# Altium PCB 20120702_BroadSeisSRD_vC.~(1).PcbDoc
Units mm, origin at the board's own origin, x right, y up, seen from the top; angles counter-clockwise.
Board outline 68.5 x 51 mm, 4 copper layers (Top Layer, Mid-Layer 1, Mid-Layer 2, Bottom Layer); 59 components, 42 nets, 186 pads, 29 vias.
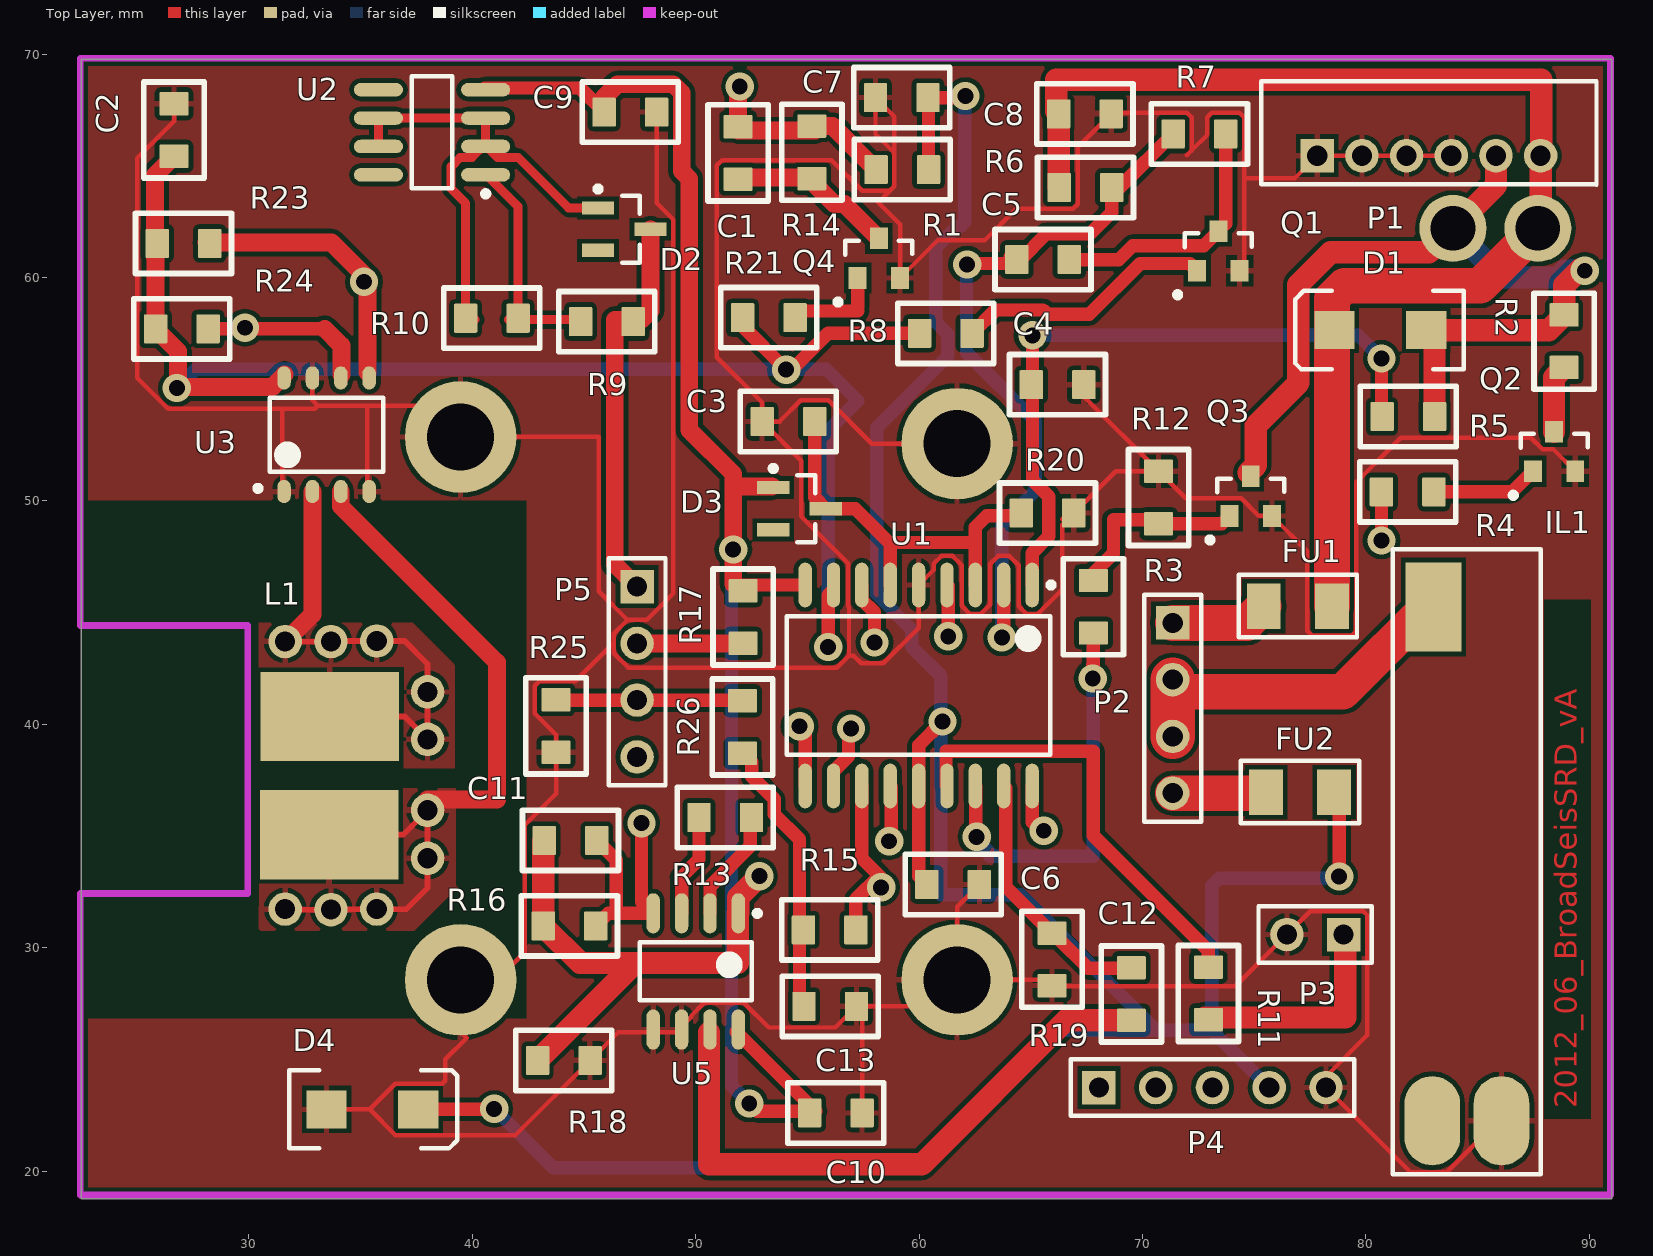
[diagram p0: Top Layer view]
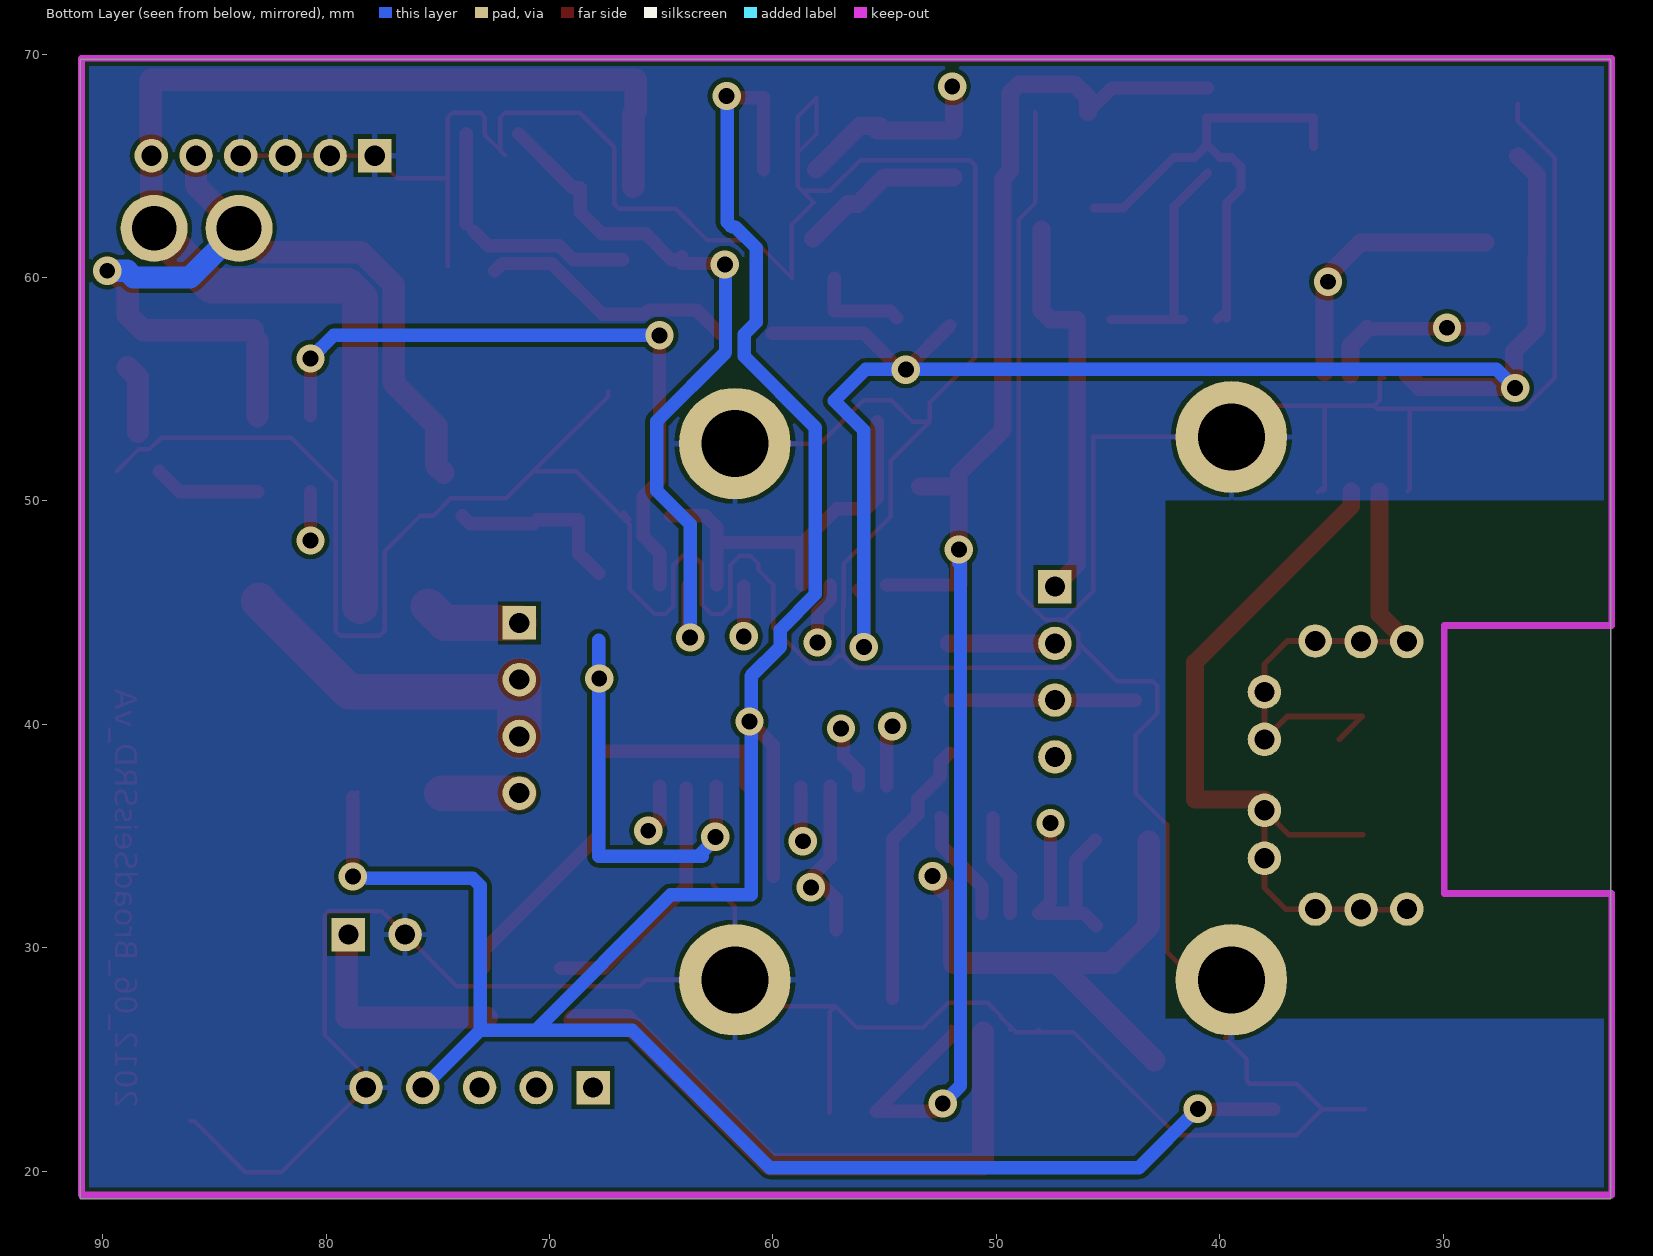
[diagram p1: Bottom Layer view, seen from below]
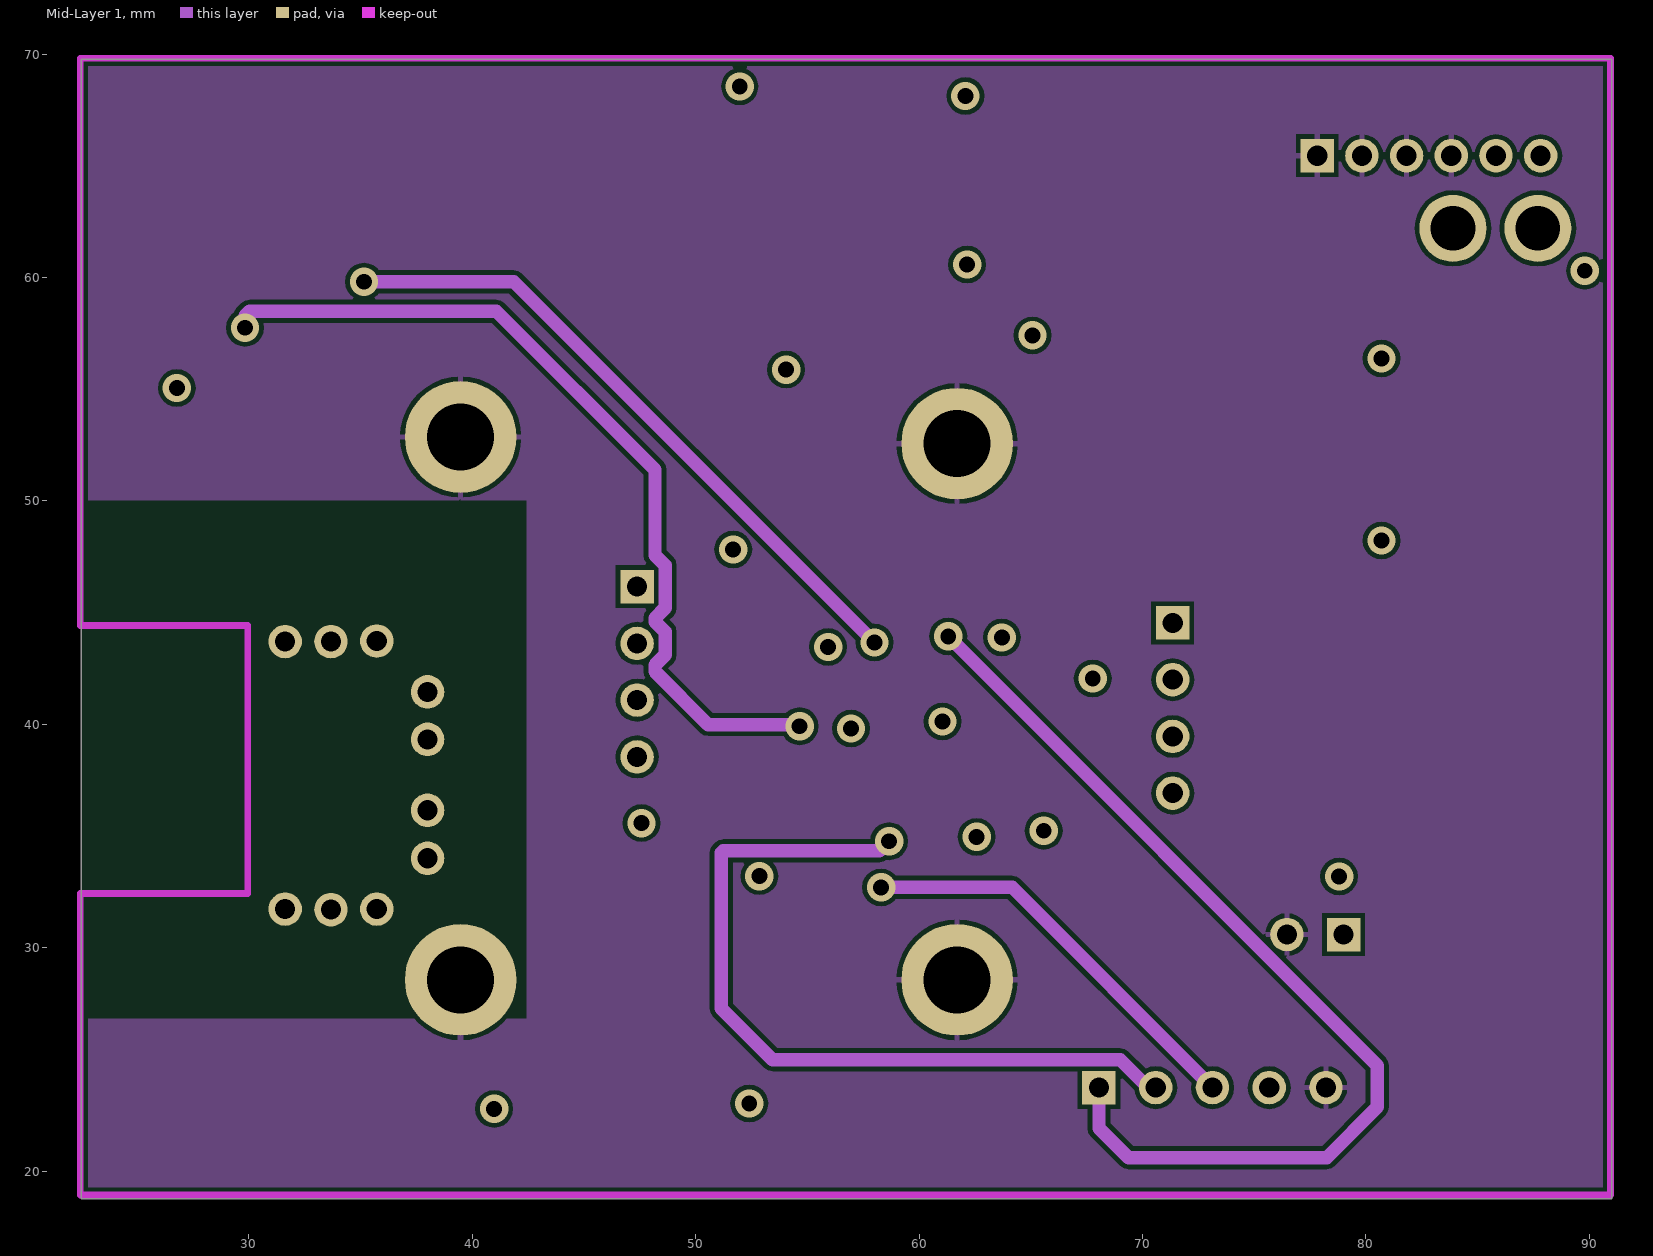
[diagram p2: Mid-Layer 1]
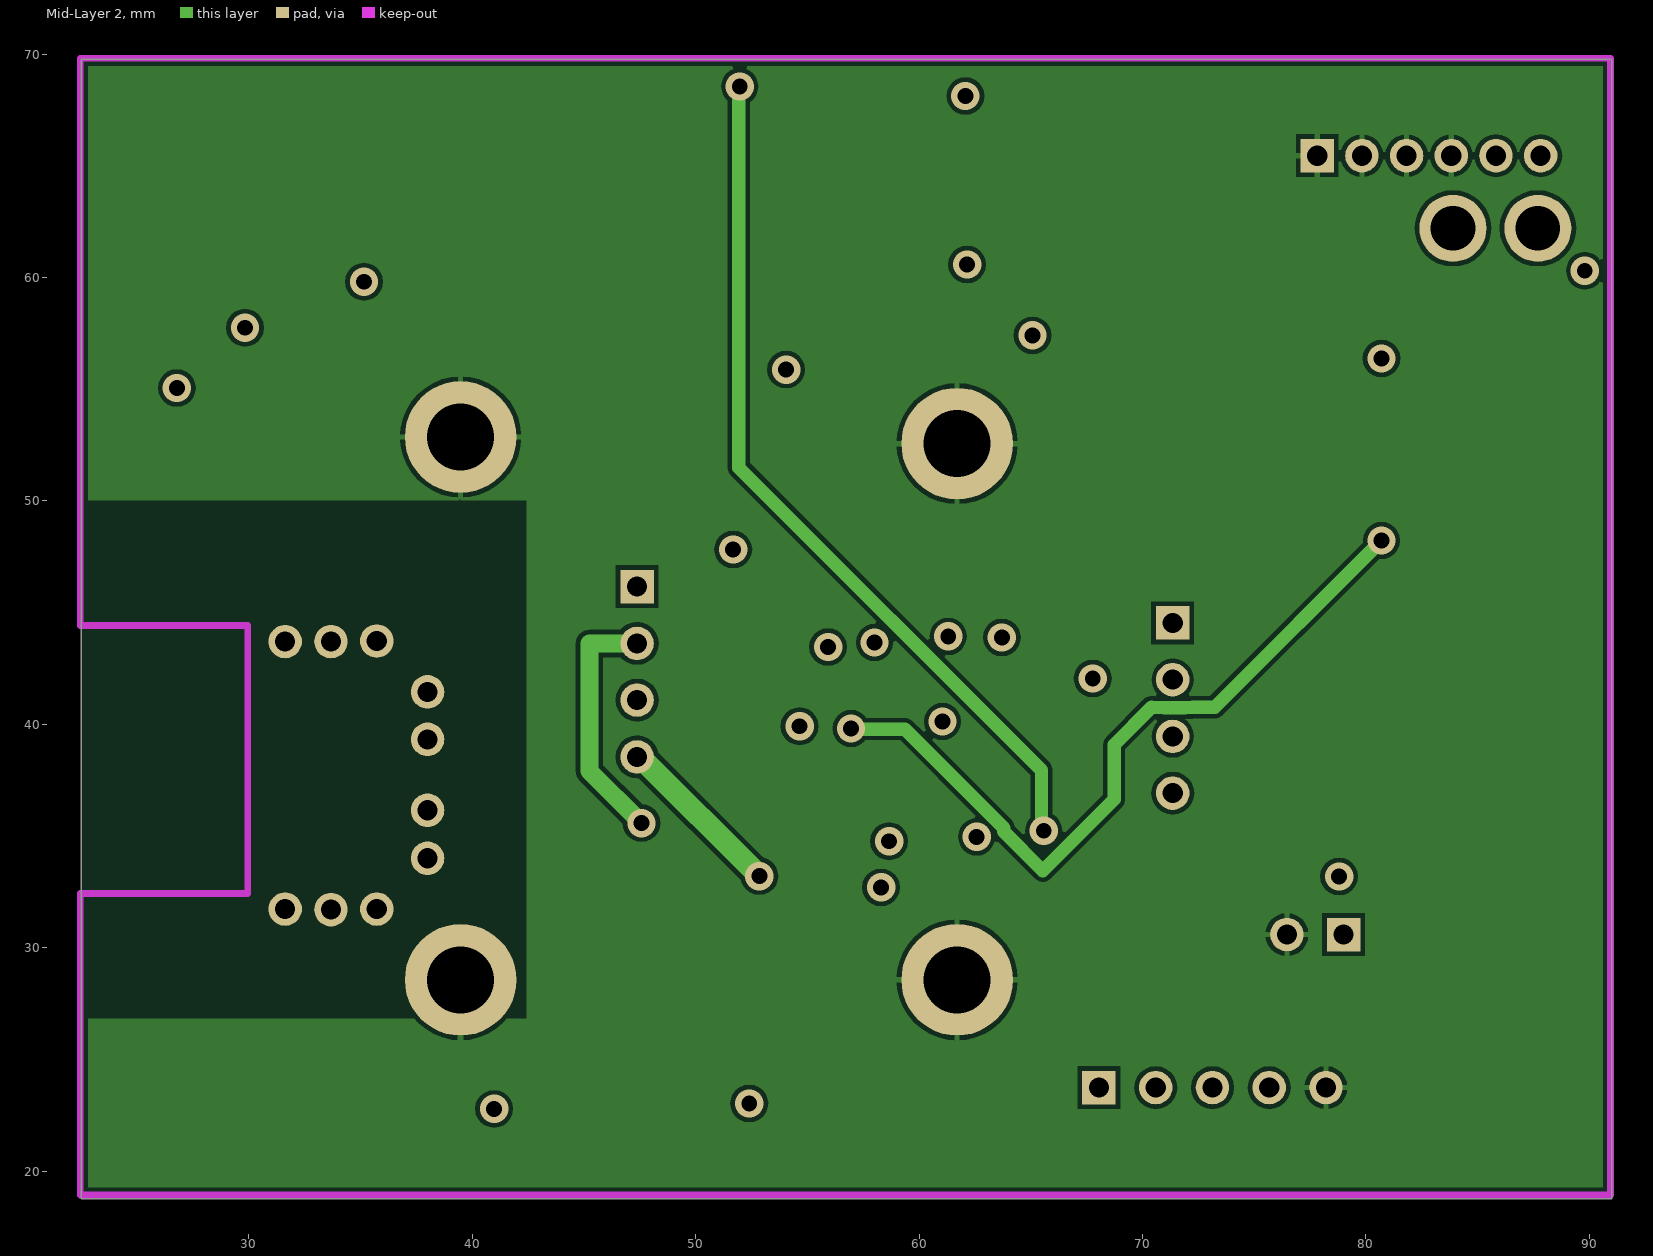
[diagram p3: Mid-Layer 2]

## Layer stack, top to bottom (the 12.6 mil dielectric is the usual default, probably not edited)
Top Layer: signal copper 0.0356
Dielectric: dielectric 0.32, FR-4, Dk 4.8
Mid-Layer 1: signal copper 0.0356
Dielectric: dielectric 0.32, FR-4, Dk 4.8
Mid-Layer 2: signal copper 0.0356
Dielectric: dielectric 0.32, FR-4, Dk 4.8
Bottom Layer: signal copper 0.0356

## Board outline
22.505,18.76 91.005,18.76 91.005,69.76 22.505,69.76

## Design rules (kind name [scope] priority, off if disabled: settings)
Clearance [All] p1: gap=0.2
HoleSize [All] p1: absolutevalues=TRUE maxlimit=5 minlimit=0.025 maxpercent=80.000 minpercent=20.000
PolygonConnect [All] p1: connectstyle=Relief reliefconductorwidth=0.254 reliefentries=4 polygonreliefangle="90 Angle"
RoomDefinition 2012_06_22_Sheet [InComponentClass('2012_06_22_Sheet')] p1: confinementstyle=ConfineIn formatcopy=TRUE lockcomponents=FALSE outline 20.986,71.285 21.117,71.153 93.055,71.153 93.055,17.297 92.819,17.06 20.855,17.06
RoutingVias [All] p1: holewidth=0.6 width=1 viastyle="Through Hole" minholewidth=0.711 minwidth=1.27 maxholewidth=0.711 maxwidth=1.27
SilkscreenOverComponentPads [All] p1: minsilkscreentomaskgap=0.254
SolderMaskExpansion [All] p1: expansion=0.102
Width [All] p1: maxlimit=2 minlimit=0.2 preferedwidth=0.6
26 further rules are at their usual default settings.

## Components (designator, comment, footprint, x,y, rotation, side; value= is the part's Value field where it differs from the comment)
C1 "Cap Semi" 1608[0603] 51.9,65.575 r90 top
C2 "Cap Semi" 1608[0603] 26.65,66.6 r270 top
C3 "Cap Semi" 1608[0603] 54.15,53.55 r0 top
C4 "Cap Semi" 1608[0603] 66.2,55.2 r180 top
C5 "Cap Semi" 1608[0603] 65.55,60.8 r180 top
C6 "Cap Semi" 1608[0603] 61.525,32.825 r180 top
C7 "Cap Semi" 1608[0603] 59.225,68.05 r0 top
C8 "Cap Semi" 1608[0603] 67.425,67.325 r180 top
C9 "Cap Semi" 1608[0603] 47.075,67.4 r180 top
C10 "Cap Semi" 1608[0603] 56.275,22.6 r180 top
C11 "Cap Semi" 1608[0603] 44.4,34.8 r0 top
C12 "Cap Semi" 1608[0603] 65.95,29.475 r90 top
C13 "Cap Semi" 1608[0603] 56.025,27.375 r180 top
D1 "RS1D" DiodeRS1D(recommendedfootprint) 80.65,57.65 r180 top
D2 "Diode BAS16" SOT-23_M 46.805,62.16 r0 top
D3 "Diode BAS16" SOT-23_M 54.65,49.65 r0 top
D4 "RS1D" DiodeRS1D(recommendedfootprint) 35.53,22.76 r0 top
FU1 "1A" FU(recommendedfootprint) 76.955,45.285 r0 top
FU2 "200mA" FU(recommendedfootprint) 77.055,36.96 r180 top
IL1 "ILS" ILS 85.975,45.25 r270 top
L1 "Inductor" INDC4532 33.625,37.7 r270 top
P1 "ConnectorToFB" "HIROSE DF3A-6P" 77.825,65.45 r0 top
P2 "Battery Pack pigtail" HDR1X4 71.355,44.535 r270 top
P3 "Connector to LED" HDR1X2 79.005,30.585 r180 top
P4 "Connector to Prog." HDR1X5 68.055,23.735 r0 top
P5 "Pressure Transducer pigtail" HDR1X4 47.38,46.16 r270 top
Q1 "NPN" transistor_SOT-23(recommendedfootprint) 73.4,61.275 r90 top
Q2 "NPN" transistor_SOT-23(recommendedfootprint) 88.425,52.3 r90 top
Q3 "MOSFET-IRLML" transistor_SOT-23(recommendedfootprint) 74.85,50.3 r90 top
Q4 "NPN" transistor_SOT-23(recommendedfootprint) 58.2,60.95 r90 top
R1 "Res3" J1-0603 59.25,64.825 r0 top
R2 "Res3" J1-0603 88.875,57.15 r90 top
R3 "Res3" J1-0603 67.805,45.26 r90 top
R4 "Res3" J1-0603 81.875,50.4 r0 top
R5 "Res3" J1-0603 81.9,53.775 r0 top
R6 "Res3" J1-0603 67.45,64.025 r180 top
R7 "Res3" J1-0603 72.55,66.425 r180 top
R8 "Res3" J1-0603 61.2,57.5 r0 top
R9 "Res3" J1-0603 46.025,58.025 r0 top
R10 "Res3" J1-0603 40.875,58.175 r180 top
R11 "Res3" J1-0603 72.95,27.95 r90 top
R12 "Res3" J1-0603 70.725,50.15 r270 top
R13 "Res3" J1-0603 51.325,35.825 r0 top
R14 "Res3" J1-0603 55.2,65.6 r90 top
R15 "Res3" J1-0603 56,30.8 r180 top
R16 "Res3" J1-0603 44.35,30.975 r0 top
R17 "Res3" J1-0603 52.125,44.8 r90 top
R18 "Res3" 1608[0603] 44.1,24.95 r180 top
R19 "Res3" J1-0603 69.5,27.925 r90 top
R20 "Res3" J1-0603 65.75,49.45 r180 top
R21 "Res3" J1-0603 53.275,58.2 r0 top
R23 "Res3" J1-0603 27.075,61.525 r0 top
R24 "Res3" J1-0603 27,57.7 r180 top
R25 "Res3" J1-0603 43.75,39.925 r90 top
R26 "Res3" J1-0603 52.1,39.875 r90 top
U1 "PIC16LF1827-I/SO" SOIC-SO18_L 59.98,41.735 r270 top
U2 "LM334D" SO8_N 38.2,66.5 r180 top
U3 "M24LR64" SO8N_N 33.48,52.96 r90 top
U5 "AD620BR" R-8D_N 50.005,28.935 r270 top

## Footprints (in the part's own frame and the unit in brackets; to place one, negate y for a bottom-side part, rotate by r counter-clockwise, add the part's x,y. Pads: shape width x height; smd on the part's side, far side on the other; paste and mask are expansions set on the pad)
1608[0603] [mm] "Chip Capacitor, Body 1.6x0.8mm, IPC High Density"
  rrect10% 1.05x1.3 smd: 1(-1.175,0) 2(1.175,0)
  silkscreen extent -2.15,-1.35 2.15,1.35
DiodeRS1D(recommendedfootprint) [mm] "DO-214-AB/SMC; 2 C-Bend Leads; Body 7.9 x 5.9 mm, inc. leads (LxW)"
  rect 1.8x1.7 smd: 1(-2.05,0) 2(2.05,0)
  silkscreen extent -3.73,-1.75 3.8,1.75
FU(recommendedfootprint) [mm] "Thru-Hole; 2 Leads"
  rect 1.52x2.03 smd: 1(-1.525,0) 2(1.525,0)
  silkscreen extent -2.65,-1.4 2.65,1.4
HDR1X2 [mm] "Connector; Header; 2 Position"
  rect 1.5x1.5 hole 0.9: 1(0,0)
  round 1.5 hole 0.9: 2(2.54,0)
  silkscreen extent -1.27,-1.27 3.81,1.27
HDR1X4 [mm] "Connector; Header; 4 Position"
  rect 1.5x1.5 hole 0.9: 1(0,0)
  round 1.5 hole 0.9: 2(2.54,0) 3(5.08,0) 4(7.62,0)
  silkscreen extent -1.27,-1.27 8.89,1.27
HDR1X5 [mm] "Connector; Header; 5 Position"
  rect 1.5x1.5 hole 0.9: 1(0,0)
  round 1.5 hole 0.9: 2(2.54,0) 3(5.08,0) 4(7.62,0) 5(10.16,0)
  silkscreen extent -1.27,-1.27 11.43,1.27
"HIROSE DF3A-6P" [mm] "Connector; Header; 6 Position"
  rect 1.5x1.5 hole 0.9: 1(0,0)
  round 1.5 hole 0.9: 2(2,0) 3(4,0) 4(6,0) 5(8,0) 6(10,0)
  round 3 hole 2: 5(6.075,-3.25) 6(9.875,-3.25)
  Top Layer lines w0.254: 9.875,-3.25 10,-2.75
  Top Layer lines w1: 6.075,-3.25 8,-1.325 8,0 ; 10,-2.75 10,0
  silkscreen extent -2.5,-1.29 12.5,3.32
ILS [mm]
  rect 4x2.5 smd: 1(0,-2.95)
  oval 4x2.5 smd: 2(23,-3) 3(23,0.1)
  silkscreen extent -2.58,-4.77 25.4,1.85
INDC4532 [mm] "Chip Inductor, Body 4.5x3.2mm, IPC High Density"
  round 1.5 hole 0.9: 1(-6.025,2.1) 1(-6,0.05) 1(-6,-2) 1(-3.75,4.375) 1(-1.625,4.375) 2(1.55,4.375) 2(3.7,4.375) 2(5.975,2.1) 2(5.975,-2) 2(6,0.05)
  rect 4x6.2 smd: 1(-2.65,0) 2(2.65,-0.025)
  Top Layer lines w0.254: -6,-2 -6,0.05 -6.025,0.075 -6.025,2.1 -6.025,3.35 -5,4.375 -3.75,4.375 -1.625,4.375 -2.65,3.35 -2.65,0 -1.625,1.025
J1-0603 [mm] "Chip Capacitor, Body 1.6x0.8mm, IPC High Density"
  rrect10% 1.05x1.3 smd: 1(-1.175,0) 2(1.175,0)
  silkscreen extent -2.15,-1.35 2.15,1.35
R-8D_N [mm] "SOIC, 8-Leads, Body 4.9x3.9mm, Pitch 1.27mm, IPC Medium Density"
  oval 1.8x0.6 smd: 1(-2.6,1.905) 2(-2.6,0.635) 3(-2.6,-0.635) 4(-2.6,-1.905) 5(2.6,-1.905) 6(2.6,-0.635) 7(2.6,0.635) 8(2.6,1.905)
  silkscreen extent -2.72,-2.5 1.3,2.88, body extent -2,-2.5 2,2.5, height 2.59
SO8_N [mm] "SOIC, 8-Leads, Body 4.9x3.9mm, Pitch 1.27mm, IPC Medium Density"
  oval 2.2x0.6 smd: 1(-2.4,1.905) 2(-2.4,-0.635) 2(-2.4,0.635) 2(2.4,-0.635) 2(2.4,0.635) 4(-2.4,-1.905) 5(2.4,-1.905) 8(2.4,1.905)
  silkscreen extent -2.53,-2.5 0.9,2.88, body extent -1.95,-2.45 1.95,2.45, height 1.75
SO8N_N [mm] "SOP, 8-Leads, Body 5.3x5.3mm, Pitch 1.27mm, IPC Medium Density"
  oval 1.04x0.6 smd: 1(-2.54,1.905) 2(-2.54,0.635) 3(-2.54,-0.635) 4(-2.54,-1.905) 5(2.54,-1.905) 6(2.54,-0.635) 7(2.54,0.635) 8(2.54,1.905)
  silkscreen extent -2.52,-2.54 1.65,3.2, body extent -2.29,-2.54 2.29,2.54, height 2.13
SOIC-SO18_L [mm] "SOIC, 18-Leads, Body 11.5x7.5mm, Pitch 1.27mm, IPC High Density"
  oval 2x0.6 smd: 1(-4.5,5.08) 2(-4.5,3.81) 3(-4.5,2.54) 4(-4.5,1.27) 5(-4.5,0) 6(-4.5,-1.27) 7(-4.5,-2.54) 8(-4.5,-3.81) 9(-4.5,-5.08) 10(4.5,-5.08) 11(4.5,-3.81) 12(4.5,-2.54) 13(4.5,-1.27) 14(4.5,0) 15(4.5,1.27) 16(4.5,2.54) 17(4.5,3.81) 18(4.5,5.08)
  silkscreen extent -4.62,-5.9 3.1,6.06, body extent -3.8,-5.95 3.8,5.95, height 2.65
SOT-23_M [mm] "SOT23, 3-Leads, Body 2.9x1.3mm, Pitch 0.95mm, Lead Span 2.5mm, IPC Low Density"
  rect 1.45x0.6 smd: 1(-1.175,0.95) 2(-1.175,-0.95) 3(1.175,0)
  silkscreen extent -1.3,-1.5 0.7,1.92, body extent -0.7,-1.5 0.7,1.5, height 1.1
transistor_SOT-23(recommendedfootprint) [mm] "SOT23, 3-Leads, Body 2.9x1.3mm, Pitch 0.95mm, Lead Span 2.5mm, IPC Low Density"
  rect 0.972x0.802 smd: 1(-0.975,0.95) 2(-0.975,-0.95) 3(0.8,0)
  silkscreen extent -2.17,-1.5 0.7,1.95, body extent -0.7,-1.5 0.7,1.5, height 1.1

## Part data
C1 C2 C3 C4 C5 C6 C7 C8 C9 C10 C11 C12 C13: "Capacitor (Semiconductor SIM Model)"
D1 D4: library part Diode, "Default Diode"
D2 D3: "Silicon Switching Diode for High-Speed Switching"
FU1 FU2: library part "Fuse 1", "Fuse"
IL1: "SPDT Subminiature Toggle Switch, Right Angle Mounting, Vertical Actuation"
P1: "Header, 6-Pin"
P2 P5: "Header, 4-Pin"
P3: "Header, 2-Pin"
P4: "Header, 5-Pin"
Q1 Q2 Q4: "NPN Bipolar Transistor"
Q3: "N-Channel MOSFET"
R1 R2 R3 R4 R5 R6 R7 R8 R9 R10 R11 R12 R13 R14 R15 R16 R17 R18 R19 R20 R21 R23 R24 R25 R26: "Resistor"
U1: "EPROM-Based 8-Bit CMOS Microcontroller, 25 Bytes RAM, 4 MHz, 18-Pin SOIC, 3.0 to 5.5V Supply Range, Extended Temperature"
U2: "Three Terminal Adjustable Current Source"
U3: "32 Kbit Serial I²C Bus EEPROM"
U5: "Low-Cost, Low-Power Instrumentation Amplifier"

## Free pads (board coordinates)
  round 5 hole 3: 1(39.48,28.56) 1(39.48,52.86) 1(61.705,28.56) 1(61.705,52.56)

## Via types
v1: diameter 1.27, hole 0.711, Top Layer to Bottom Layer, 29 vias

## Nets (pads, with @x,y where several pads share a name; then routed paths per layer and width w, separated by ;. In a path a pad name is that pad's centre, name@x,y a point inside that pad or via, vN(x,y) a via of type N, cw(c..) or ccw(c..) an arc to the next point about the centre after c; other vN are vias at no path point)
ACTIVATION+: FU1.1 P2.1 | length 4.4
  Top Layer w1.6: P2.1 74.68,44.535 FU1.1
ADJ: R9.1 R10.1 U2.1 | length 10.4
  Top Layer w0.4: U2.1@40.55,64.67 42.05,63.17 R10.1 ; R10.1@41.63,58.11 R9.1@44.88,58.11
ANA_PRESSURE: C12.2 R19.2 U1.17 | length 11.4
  Top Layer w0.2: U1.17 U1.17@63.88,37.145 ; 63.88,33.66 63.905,33.685
  Top Layer w0.6: U1.17@63.88,37.145 63.88,33.66 63.88,32.72 C12.2 ; C12.2@66.2,30.45 67.575,29.075 R19.2@69.5,29.075
B7: P4.2 U1.13 | length 38.1
  Top Layer w0.2: U1.13 U1.13@58.755,37.19
  Top Layer w0.6: v1(58.659,34.764) 58.659,35.014 58.755,35.11 U1.13@58.755,37.19
  Mid-Layer 1 w0.6: v1(58.659,34.764) 58.23,34.335 51.235,34.335 51.15,34.25 51.15,27.275 53.44,24.985 69.012,24.985 70.262,23.735 P4.2
CHECK-FIRE: R4.1 U1.11 | length 39
  Top Layer w0.2: v1@56.84,39.695 v1(56.955,39.81)
  Top Layer w0.6: U1.11 56.17,37.9 56.84,38.57 v1@56.84,39.695 ; v1(80.7,48.225) R4.1
  Mid-Layer 2 w0.6: v1@57.03,39.785 59.36,39.785 63.79,35.355 63.79,35.2 65.543,33.447 68.73,36.635 68.73,39.085 70.405,40.76 70.967,40.735 71.892,40.735 72.255,40.76 73.235,40.76 v1(80.7,48.225)
COIL1: L1.2 U3.3 | length 34.9
  Top Layer w0.254: L1.2@31.65,31.7 L1.2@33.675,31.7 ; L1.2@33.6,35.05 36.9,35.05 38,36.15 38,34 38,32.675 37.05,31.725 35.725,31.725 L1.2@33.7,31.725
  Top Layer w0.6: L1.2@31.625,31.725 L1.2@31.65,31.7 ; L1.2@33.675,31.7 L1.2@33.7,31.725
  Top Layer w0.8: U3.3 34.115,49.76 41.1,42.775 41.1,36.625 L1.2@38,36.625
COIL2: L1.1 U3.2 | length 7.2
  Top Layer w0.8: L1.1@31.625,43.7 32.845,44.92 U3.2
FB1: C8.2 D1.2 FU1.2 P1.6 R6.2 | length 54.3
  Top Layer w1: R6.2@66.25,64.05 C8.2 66.141,67.434 66.141,68.85 87.85,68.85 87.85,65.475 P1.6@87.825,65.45
  Top Layer w1.6: FU1.2 78.48,59.06 79.045,59.625 85.125,59.625 P1.6@87.7,62.2
FB2: D1.1 P1.5 Q3.3 R2.2 R5.2 | length 35.8
  Top Layer w1: Q3.3@74.751,51.265 75.075,51.589 75.075,53.375 76.98,55.28 76.98,59.681 78.424,61.125 82.825,61.125 P1.5@83.9,62.2 ; R5.2 D1.1@83.075,57.15 ; D1.1@83.275,57.635 88.185,57.635 R2.2 88.875,59.65 v1@89.6,60.375
  Bottom Layer w1: P1.5@83.9,62.2 86.1,60 88.611,60 88.911,60.3 v1(89.8,60.3)
FIRE: R3.1 U1.16 | length 21.7
  Top Layer w0.2: U1.16 U1.16@62.53,37.225
  Top Layer w0.6: U1.16@62.53,37.225 62.53,34.71 62.605,34.785 62.655,34.785 62.58,34.86 v1(62.58,34.96) ; v1(67.775,42.05) 67.775,42.65 67.805,42.68 R3.1@67.805,43.75
  Bottom Layer w0.6: v1@62.53,34.71 62.605,34.785 62.655,34.785 63.28,34.16 ; 63.155,34.085 67.805,34.085 67.805,43.76 67.8,43.755 67.8,42.075 v1(67.775,42.05)
FLASH_LED: R11.2 U1.15 | length 20
  Top Layer w0.2: U1.15@61.205,37.28 U1.15
  Top Layer w0.6: U1.15@61.205,37.28 61.205,38.785 67.805,38.785 67.805,35.02 72.95,29.875 R11.2
GND: C2.1 C3.1 C4.1 C6.1 C7.1 C8.1 C9.1 C10.1 C12.1 C13.1 D4.1 IL1.3 P1.1 P1.2 P1.3 P1.4 P3.2 P4.5 pad.1 Q1.2 Q2.2 Q3.2 Q4.2 R12.1 R18.1 R20.1 R25.1 U1.5 U3.1 U3.4 U3.7 U5.5 U5.6 | length 358.9
  Top Layer w0.2: C2.1 26.65,66.994 25,65.344 25,55.503 26.388,54.115 31.485,54.115 ; U3.1 31.485,50.51 31.485,54.115 ; U3.7@32.644,55.5 U3.7 32.845,54.505 33.09,54.26 ; D4.1 35.406,22.76 ; U3.4 35.3,50.505 35.3,54.26 ; U3.4@35.41,50.57 U3.4@35.605,50.375 ; pad.1@38.79,27.87 38.79,26.913 39.748,25.955 38.79,24.998 38.79,24.04 38.66,23.91 36.556,23.91 35.406,22.76 ; pad.1@39.48,28.56 pad.1@40.45,29.53 ; pad.1@41.11,28.56 42.35,29.8 42.35,35.494 43.75,36.894 R25.1 43.75,39.531 42.8,40.481 42.8,41.719 43.006,41.925 44.605,41.925 46.33,43.65 ; U5.5 U5.5@48.215,26.22 ; C9.1 48.25,63.339 49.005,62.584 49.005,45.861 47.814,44.67 46.945,44.67 ; U5.6 U5.6@49.305,26.4 ; C10.1 57.45,27.125 C13.1 ; pad.1@60.52,27.375 C13.1 ; pad.1@61.705,52.56 57.884,52.56 55.944,54.5 54.706,54.5 53.756,53.55 C3.1 ; C6.1 61.705,31.83 61.705,28.56 65.69,28.56 C12.1 65.975,28.275 74.155,28.275 P3.2 ; R20.1@66.405,49.185 R20.1@66.705,49.485 ; C4.1@67.375,54.914 67.375,54.675 R12.1 ; C8.1 67.1,65.825 67.1,63.281 66.894,63.075 64.35,63.075 62.95,61.675 60.85,61.675 Q4.2 59.15,62.381 58.175,63.356 58.694,63.875 ; C8.1@68.65,67.375 71.994,67.375 72.2,67.169 72.2,65.681 ; Q1.2@74.55,60.5 74.55,64.451 ; P3.2@77.081,30.585 P3.2 ; P1.4 P1.3 P1.2 P1.1 76.826,64.451 74.55,64.451 ; IL1.3 85.917,22.25 83.617,19.95 82,19.95 P4.5 78.215,24.235 80.055,26.075 80.055,31.459 79.879,31.635 77.515,31.635 P3.2 ; Q2.2 88.4,52.3 87.914,52.3 87.389,52.825 81.556,52.825 79.58,50.849 79.58,44.186 79.364,43.97 77.596,43.97 77.38,44.186 77.38,47.745 Q3.2 75.211,49.325 74.425,50.111 71.939,50.111 R12.1 ; 31.485,54.115 32.945,54.115 33.09,54.26 ; 33.09,54.26 35.3,54.26 ; 35.3,54.26 38.08,54.26 39.48,52.86 45.665,52.86 45.665,45.95 46.945,44.67 ; 35.406,22.76 36.556,21.61 41.935,21.61 R18.1 46.545,26.22 U5.5@48.215,26.22 ; 46.33,43.65 46.33,44.055 46.945,44.67 ; 46.33,43.65 46.33,43.185 46.99,42.525 56.317,42.525 56.865,43.073 ; U5.5@48.215,26.22 49.125,26.22 U5.6@49.305,26.4 ; U5.6@49.305,26.4 49.796,26.891 49.796,26.939 50.391,27.535 52.159,27.535 53.269,26.425 56.25,26.425 C13.1 ; C3.1 54.725,51.8 54.725,49.301 56.84,47.186 56.84,45.286 56.865,45.261 56.865,43.073 ; C3.1 52.975,54.401 50.95,56.426 50.95,65.019 51.181,65.25 56.081,65.25 57.456,63.875 58.694,63.875 ; 56.865,43.073 57.07,43.073 57.418,42.725 58.392,42.725 59.98,44.313 U1.5 60.65,46.905 60.65,47.184 61.001,47.535 61.499,47.535 61.905,47.129 61.905,45.301 62.271,44.935 62.769,44.935 63.19,45.356 63.19,47.184 63.541,47.535 64.039,47.535 64.46,47.114 64.46,45.286 64.811,44.935 65.309,44.935 66.405,46.031 66.405,48.93 R20.1 68.8,51.325 R12.1 ; 58.694,63.875 58.9,64.081 58.9,65.569 ; 58.9,65.569 58.9,67.2 C7.1 58.05,66.419 58.9,65.569 ; 72.2,65.681 72.9,66.381 72.9,67.169 73.106,67.375 74.344,67.375 74.55,67.169 74.55,64.451 ; 72.2,65.681 71.994,65.475 72.2,65.681
IN+: D2.3 P5.1 R9.2 | length 17.8
  Top Layer w0.8: P5.1 46.38,47.16 46.38,58.11 47.58,58.11 47.98,58.51 D2.3
IN-: P5.3 R25.2 R26.2 | length 8.3
  Top Layer w0.6: R25.2@43.77,41.08 P5.3 R26.2@52.07,41.08
ISENS_CHECK: P4.3 R15.1 U1.12 | length 25.7
  Top Layer w0.6: R15.1 57.175,32.175 58.225,33.225 57.44,34.01 U1.12
  Mid-Layer 1 w0.6: v1(58.3,32.7) 64.17,32.7 P4.3
LED+: P3.1 R11.1 | length 10
  Top Layer w1: R11.1@72.8,26.875 79.08,26.875 79.08,30.51 P3.1
LP0-VDD: C2.2 R8.1 R21.1 R23.1 R24.2 U1.8 U3.8 | length 71.4
  Top Layer w0.2: U1.8@56.17,46.025 U1.8
  Top Layer w0.6: R21.1@52.075,57.85 v1(54.05,55.875) 54.301,55.875 55.926,57.5 R8.1 ; v1(55.93,43.46) 55.93,45.785 U1.8@56.17,46.025
  Top Layer w0.8: C2.2 25.8,64.575 25.8,60.9 25.825,60.875 R24.2 26.825,56.7 26.825,55.1 31.05,55.1 U3.8@31.6,55.65
  Bottom Layer w0.6: v1(26.775,55.05) 27.61,55.885 55.84,55.885 57.25,54.475 55.93,53.155 v1(55.93,43.46)
MCLR/: P4.1 U1.4 | length 47.1
  Top Layer w0.2: U1.4 U1.4@61.305,46.18
  Top Layer w0.6: v1(61.305,43.935) U1.4@61.305,46.18
  Mid-Layer 1 w0.6: v1(61.305,43.935) 80.515,24.725 80.515,22.865 78.25,20.6 69.375,20.6 68.055,21.92 P4.1
NetC1_1: C1.1 Q4.3 R14.1 | length 7.4
  Top Layer w0.8: C1.1@51.905,64.475 55.025,64.475 56.205,63.295 56.655,63.295 Q4.3
NetC3_2: C3.2 D3.3 R20.2 U1.3 U1.6 | length 18.1
  Top Layer w0.6: C3.2 55.325,50.15 D3.3 57.145,49.65 58.71,48.085 ; U1.6 58.71,48.085 ; 62.445,48.135 58.76,48.135 58.71,48.085 ; U1.3 62.52,48.825 63.03,49.335 R20.2@64.575,49.335
NetC5_1: C5.1 Q1.3 R7.1 | length 11.2
  Top Layer w0.6: C5.1 68.944,60.8 69.569,61.425 72.75,61.425 Q1.3 ; Q1.3@73.725,62.4 R7.1
NetC13_2: C13.2 R15.2 R26.1 | length 12
  Top Layer w0.6: R26.1 52.502,38.298 52.502,37.674 53.525,36.651 53.525,35.975 54.65,34.85 C13.2@54.65,27.725
NetIL1_1: IL1.1 P2.2 P2.3 | length 16.1
  Top Layer w0.2: P2.2 71.89,41.46
  Top Layer w1.6: 71.89,41.46 78.972,41.46 83.005,45.493 IL1.1@83.005,45.535
  Top Layer w2: P2.3 P2.2
NetQ1_1: Q1.1 R8.2 | length 11.7
  Top Layer w0.6: R8.2 63.42,58.545 65.55,58.545 65.745,58.35 67.625,58.35 69.9,60.625 72.125,60.625 Q1.1
NetQ2_1: Q2.1 R4.2 | length 4.8
  Top Layer w0.6: R4.2 86.55,50.4 Q2.1
NetQ2_3: Q2.3 R2.1 | length 3.1
  Top Layer w1: Q2.3 88.425,55.525 R2.1
NetQ3_1: Q3.1 R3.2 R12.2 | length 7.9
  Top Layer w0.6: R3.2@67.805,46.76 68.705,47.66 68.705,49.16 R12.2@70.54,49.16 ; R12.2 73.55,48.975 Q3.1
NetQ4_1: Q4.1 R21.2 | length 4.2
  Top Layer w0.6: R21.2 54.75,58.5 57.25,58.5 ; 57.25,58.675 Q4.1
NetR13_1: R13.1 U5.3 | length 4.6
  Top Layer w0.6: U5.3 49.37,33.13 49.35,33.15 50.15,33.95 R13.1
NetR13_2: R13.2 U5.2 | length 5.1
  Top Layer w0.6: U5.2 50.64,32.74 52.45,34.55 52.45,35.775 R13.2
NetR19_1: R19.1 U5.7 | length 26.9
  Top Layer w1: U5.7@50.596,26.201 50.596,20.3 60.125,20.3 66.575,26.75 R19.1@68.875,26.75
OUT+: C11.2 P5.2 R16.2 R17.1 U5.4 | length 26.6
  Top Layer w0.6: R16.2 46.085,31.535 46.45,31.535 ; C11.2 46.45,33.925 46.45,31.535 ; v1(47.575,35.575) 47.575,32.06 U5.4 46.45,31.535
  Top Layer w0.8: P5.2 52.12,43.62 R17.1
  Mid-Layer 2 w0.8: P5.2 45.24,43.62 45.24,37.91 v1(47.575,35.575)
OUT-: C11.1 P5.4 R16.1 R18.2 U5.1 | length 31.3
  Top Layer w1: R18.2 47.285,29.31 ; C11.1@43.175,34.75 R16.1 44.84,29.31 47.285,29.31 ; U5.1@51.88,31.505 51.88,29.31 47.285,29.31 ; U5.1 51.91,32.26 v1(52.85,33.2)
  Mid-Layer 2 w1: P5.4 47.51,38.54 v1(52.85,33.2)
PCB+: FU2.2 P2.4 | length 3.5
  Top Layer w1.6: P2.4 FU2.2@74.825,36.915
SCLK: R24.1 U1.10 U3.6 | length 49.7
  Top Layer w0.6: R24.1 33.395,57.7 ; v1(54.655,39.91) 54.9,39.665 U1.10
  Top Layer w0.8: 33.395,57.7 34.14,56.955 U3.6@34.14,55.65
  Mid-Layer 1 w0.2: v1(29.825,57.75) v1@29.825,58.28
  Mid-Layer 1 w0.6: v1@29.825,58.28 30.03,58.485 41.08,58.485 48.18,51.385 48.18,47.567 48.63,47.117 48.63,45.203 48.18,44.753 48.18,44.588 48.63,44.138 48.63,43.102 48.18,42.652 48.18,42.36 50.555,39.985 v1@54.855,39.985
SDA: R23.2 U1.7 U3.5 | length 44.1
  Top Layer w0.6: U1.7 57.44,45.575 58.005,45.01 v1(58.005,43.66)
  Top Layer w0.8: R23.2@28.105,61.56 33.705,61.56 35.305,59.96 U3.5@35.305,55.755
  Mid-Layer 1 w0.6: v1(35.155,59.81) 41.855,59.81 v1@57.755,43.91
V+: C9.2 C10.2 D3.1 R17.2 U1.9 U2.4 U5.8 | length 73.8
  Top Layer w0.2: R17.2@51.68,46.285 R17.2@51.73,46.235 ; U5.8@51.812,26.238 U5.8 U5.8@52.025,26.45 ; v1(52.4,23.025) v1@52.75,22.675
  Top Layer w0.6: U2.4@40.55,68.48 44.82,68.48 C9.2 ; R17.2@51.73,46.235 U1.9 ; U5.8@51.812,26.238 55.375,22.675 v1@52.75,22.675
  Top Layer w0.8: C9.2 45.9,68.05 46.5,68.65 48.993,68.65 49.375,68.268 49.375,64.762 49.715,64.422 49.715,53.175 51.68,51.21 51.68,50.65 ; R17.2@51.68,46.285 v1(51.68,47.825) 51.68,50.65 ; D3.1@53.425,50.65 51.68,50.65
  Bottom Layer w0.6: v1(51.68,47.825) 51.68,47.23 51.65,47.2 51.65,48.115 51.605,48.16 51.605,23.82 v1(52.4,23.025)
V-: D2.1 R10.2 U2.2 | length 22.8
  Top Layer w0.4: U2.2@35.8,65.865 35.8,67.135 40.6,67.135 40.6,65.99 U2.2@40.55,65.94 ; R10.2 39.7,63.32 39.05,63.97 39.05,64.96 39.46,65.37 39.98,65.37 U2.2@40.55,65.94 ; R10.2@39.895,58.345 R10.2@40.13,58.11 ; D2.1 44.31,63.11 42.05,65.37 41.12,65.37 U2.2@40.55,65.94
VBAT1: C1.2 R1.1 R14.2 U1.18 | length 50
  Top Layer w0.6: U1.18 65.06,35.605 v1@65.28,35.385
  Top Layer w0.8: C1.2 51.9,68.475 v1(51.975,68.55) ; C1.2@51.905,66.585 R14.2@55.355,66.585 ; R14.2 56.125,66.775 R1.1
  Mid-Layer 2 w0.6: v1(51.975,68.55) 51.93,68.505 51.93,51.485 65.48,37.935 v1@65.48,35.11
  other v1: 65.58,35.235
VBAT2: C5.2 R6.1 R7.2 U1.2 | length 33.6
  Top Layer w0.6: v1(62.153,60.578) 62.153,60.387 62.15,60.387 62.15,60.625 64.078,60.625 C5.2@64.078,60.928 ; v1(63.705,43.885) 63.79,43.97 U1.2 ; C5.2 64.55,60.8 65.7,61.95 67.65,61.95 68.625,62.925 R6.1 68.975,64.025 R7.2
  Bottom Layer w0.6: v1@62.125,60.578 62.125,56.64 65.205,53.56 65.205,50.46 63.705,48.96 v1(63.705,43.885)
VDD: C6.2 C7.2 D4.2 FU2.1 P4.4 R1.2 U1.14 | length 122.1
  Top Layer w0.2: v1@40.955,22.76 v1(40.98,22.785) ; U1.14 U1.14@60.08,37.135 ; FU2.1 FU2.1@78.805,36.735
  Top Layer w0.6: D4.2 v1@40.955,22.76 ; C6.2@59.98,33.195 U1.14 59.98,39.055 v1(61.05,40.125) ; R1.2 60.425,68.025 C7.2 62,68.05 v1(62.075,68.125) ; v1(78.805,33.185) FU2.1@78.805,36.735
  Bottom Layer w0.6: v1(40.98,22.785) 43.615,20.15 60.145,20.15 66.305,26.31 70.625,26.31 ; v1@62.045,68.125 62.045,62.47 61.835,62.26 61.68,62.26 60.75,61.33 60.75,57.995 61.29,57.455 61.29,56.47 58.105,53.285 58.105,45.813 59.68,44.238 59.68,43.46 60.98,42.16 60.98,32.36 64.575,32.36 70.625,26.31 ; v1@62.045,68.155 v1(62.075,68.125) ; P4.4 73.1,26.31 ; 78.155,33.11 73.445,33.11 73.1,32.765 73.1,26.31 ; 70.625,26.31 73.1,26.31
VFIRE: C4.2 R5.1 U1.1 | length 30.4
  Top Layer w0.6: U1.1 65.06,47.665 65.805,48.41 65.805,50.195 65.08,50.92 v1(65.08,57.41) ; R5.1@80.7,53.8 v1(80.7,56.375)
  Bottom Layer w0.6: v1(65.08,57.41) 79.665,57.41 v1(80.7,56.375)
pads on no net: D2.2 D3.2 IL1.2 U2.5 U2.8

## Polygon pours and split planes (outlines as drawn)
GND on Top Layer "Top Layer-No Net" (solid, pour order 8): 22.455,69.81 90.955,69.81 90.955,18.925 22.455,18.925 22.455,26.82 22.45,26.825 42.45,26.825 42.45,50.025 22.7,50.025
COIL1 on Top Layer "Top Layer-No Net" (solid, pour order 6): 30.45,30.8 30.5,30.75 37.1,30.75 37.4,30.75 39.35,32.7 39.25,32.8 39.25,37.125 30.525,37.125
COIL2 on Top Layer "Top Layer-No Net" (solid, pour order 12): 30.45,44.575 30.475,44.55 37.05,44.55 37.325,44.55 39.125,42.75 39.225,42.65 39.225,38.025 30.6,38.025 30.45,38.175
GND on Mid-Layer 1 "Top Layer-No Net" (solid, pour order 12): 22.455,69.81 90.955,69.81 90.955,18.925 22.455,18.925 22.45,18.93 22.45,26.825 42.45,26.825 42.45,50.025 22.45,50.025
GND on Mid-Layer 2 "Top Layer-No Net" (solid, pour order 14): 22.455,69.81 90.955,69.81 90.955,18.925 22.455,18.925 22.455,26.82 22.45,26.825 42.45,26.825 42.45,50.025 22.45,50.025
GND on Bottom Layer "Top Layer-No Net" (solid, pour order 16): 22.455,69.81 90.955,69.81 90.955,18.925 22.455,18.925 22.45,18.93 22.45,26.825 42.45,26.825 42.45,50.025 22.45,50.025

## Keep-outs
Keep-Out Layer:
  lines w0.3: 22.455,18.925 90.955,18.925 90.955,69.81 22.455,69.81 22.455,60.36 22.455,52.422 22.455,51.397 22.455,44.425 29.955,44.425 29.955,39.66 29.955,32.425 22.455,32.425 22.455,18.925

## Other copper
Top Layer:
  text "2012_06_BroadSeisSRD_vA" at 89.45,22.8 h1 r90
